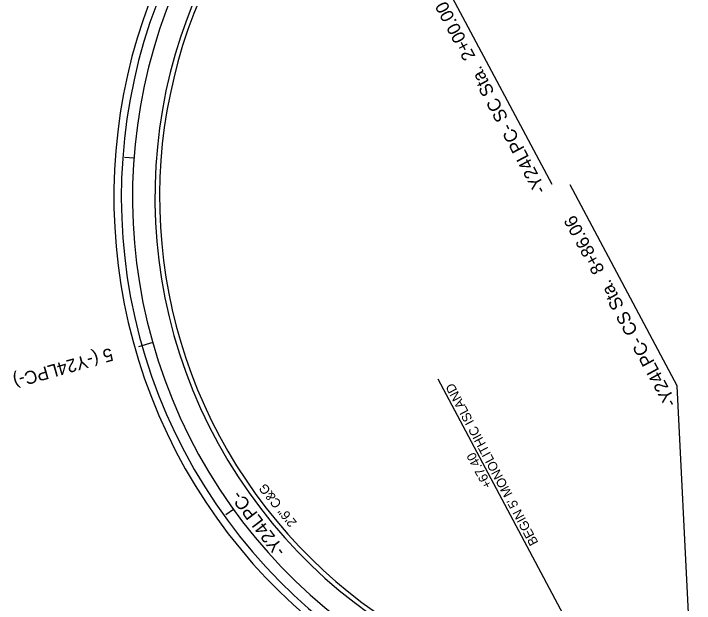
# Model space of a CAD drawing. Extents: x 2389694 to 2405615, y 546931 to 573532.
# Drawn here: x 2402068.5 to 2402433.7, y 570357.8 to 570674.4 of the extents above; entities that cross this region are included whole.
import ezdxf

# ---------------------------------------------------------------- set-up
doc = ezdxf.new("R2010")
doc.units = 0
for name, color, linetype in [('Prop Conc 2ft 6in Curb and Gutter', 7, 'Continuous'), ('Prop Dimension Text', 7, 'Continuous'), ('Prop DSN Text', 7, 'Continuous'), ('Prop EOT', 7, 'Continuous'), ('Prop Horizontal Alignment', 7, 'Continuous'), ('Prop Horizontal Alignment Curve and Spiral Data', 7, 'Continuous'), ('Prop Horizontal Alignment Tick Large', 7, 'Continuous'), ('Prop Horizontal Alignment Tick Small', 7, 'Continuous')]:
    doc.layers.add(name, color=color, linetype=linetype)

msp = doc.modelspace()

# ---------------------------------------------------------------- linework, layer by layer
at = {"layer": 'Prop Conc 2ft 6in Curb and Gutter'}
msp.add_arc((2402419.3, 570575.99), 272.5, 151.0902, 272.8811, dxfattribs=at)
at = {"layer": 'Prop DSN Text'}
msp.add_line((2402403.61, 570276.33), (2402296.27, 570478.2), dxfattribs=at)
at = {"layer": 'Prop EOT'}
for radius, start, end in [(293, 135.9178, 271.0318), (275, 135.9178, 272.8811), (297, 141.132, 269.5038)]:
    msp.add_arc((2402419.3, 570575.99), radius, start, end, dxfattribs=at)
at = {"layer": 'Prop Horizontal Alignment'}
msp.add_arc((2402419.3, 570575.99), 287, 135.9178, 272.8811, dxfattribs=at)
at = {"layer": 'Prop Horizontal Alignment Curve and Spiral Data'}
for p, q in [((2402298.73, 570692.76), (2402357.17, 570582.86)), ((2402424.41, 570474.57), (2402367.04, 570582.46)), ((2402433.65, 570290.85), (2402424.41, 570474.57))]:
    msp.add_line(p, q, dxfattribs=at)
at = {"layer": 'Prop Horizontal Alignment Tick Large'}
msp.add_line((2402143.16, 570497.81), (2402135.46, 570495.63), dxfattribs=at)
at = {"layer": 'Prop Horizontal Alignment Tick Small'}
for p, q in [((2402133.06, 570596.79), (2402128.07, 570597.15)), ((2402186.45, 570408.22), (2402182.39, 570405.3))]:
    msp.add_line(p, q, dxfattribs=at)

# ---------------------------------------------------------------- texts
at = {"layer": 'Prop Dimension Text'}
msp.add_text('2\'6" C&G', height=5, rotation=128.9286, dxfattribs=at).set_placement((2402220.7, 570401.31))
at = {"layer": 'Prop DSN Text'}
for s, p in [("BEGIN 5' MONOLITHIC ISLAND", (2402350.15, 570390.46)), ('+67.40', (2402325.35, 570421.15))]:
    msp.add_text(s, height=5, rotation=118, dxfattribs=at).set_placement(p)
at = {"layer": 'Prop Horizontal Alignment Curve and Spiral Data'}
for s, rotation, p in [('-Y24LPC- SC Sta.  2+00.00', 117.9537, (2402354.49, 570579.87)), ('-Y24LPC- CS Sta.  8+86.06', 118.5273, (2402424.52, 570465.52)), ('5 (-Y24LPC-)', 195.8089, (2402120.69, 570495.06)), ('-Y24LPC-', 127.2015, (2402214.88, 570386.18))]:
    msp.add_text(s, height=7, rotation=rotation, dxfattribs=at).set_placement(p)

doc.saveas('drawing.dxf')
